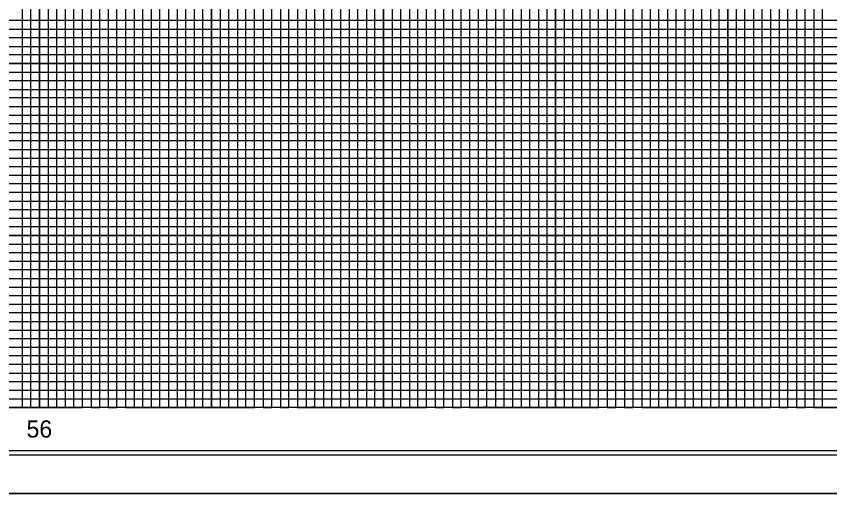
# Model space of a CAD drawing. Extents: x 1755181 to 1757273, y 729911 to 735411.
# Drawn here: x 1755934.2 to 1756407, y 733199.6 to 733488.3 of the extents above; entities that cross this region are included whole.
import ezdxf

# ---------------------------------------------------------------- set-up
doc = ezdxf.new("R2010")
doc.units = 0
for name, color, linetype in [('Exist Vertical Profile Horizontal Axis Label Major', 7, 'Continuous'), ('Scratch_Level_3', 7, 'Continuous'), ('Sheet Cutting Line CELL', 7, 'Continuous'), ('Sheet DOT Grid CELL', 7, 'Continuous'), ('Sheet Plot Border Inside CELL', 7, 'Continuous'), ('Sheet Plot Border Outside CELL', 7, 'Continuous'), ('Sheet Profile CELL', 7, 'Continuous'), ('Sheet Profile Grid Major CELL', 7, 'Continuous'), ('Sheet Profile Grid Middle CELL', 7, 'Continuous'), ('Sheet Profile Grid Minor CELL', 7, 'Continuous')]:
    doc.layers.add(name, color=color, linetype=linetype)

msp = doc.modelspace()

# ---------------------------------------------------------------- linework, layer by layer
at = {"layer": 'Scratch_Level_3'}
msp.add_lwpolyline([(1755397.67, 733760.78), (1756847.67, 733760.78), (1756847.67, 733260.78), (1755397.67, 733260.78)], close=True, dxfattribs=at)
at = {"layer": 'Sheet Cutting Line CELL'}
msp.add_line((1755180.67, 733210.78), (1756864.67, 733210.78), dxfattribs=at)
at = {"layer": 'Sheet DOT Grid CELL'}
for p, q in [((1755947.67, 733760.78), (1755947.67, 733260.78)), ((1755997.67, 733760.78), (1755997.67, 733260.78)), ((1756047.67, 733760.78), (1756047.67, 733260.78)), ((1756097.67, 733760.78), (1756097.67, 733260.78)), ((1756147.67, 733760.78), (1756147.67, 733260.78)), ((1756197.67, 733760.78), (1756197.67, 733260.78)), ((1756247.67, 733760.78), (1756247.67, 733260.78)), ((1756297.67, 733760.78), (1756297.67, 733260.78)), ((1756347.67, 733760.78), (1756347.67, 733260.78)), ((1756397.67, 733760.78), (1756397.67, 733260.78)), ((1755347.67, 733460.78), (1756847.56, 733460.78)), ((1755347.67, 733410.78), (1756847.56, 733410.78)), ((1755347.67, 733360.78), (1756847.56, 733360.78)), ((1755347.67, 733310.78), (1756847.56, 733310.78))]:
    msp.add_line(p, q, dxfattribs=at)
at = {"layer": 'Sheet Plot Border Inside CELL'}
msp.add_lwpolyline([(1755193.67, 733233.23), (1756860.17, 733233.23), (1756860.17, 734288.33), (1755193.67, 734288.33)], close=True, dxfattribs=at)
at = {"layer": 'Sheet Plot Border Outside CELL'}
for points in [[(1755180.67, 733210.78), (1756864.67, 733210.78), (1756864.67, 734310.78), (1755180.67, 734310.78)], [(1755180.67, 732110.78), (1756864.67, 732110.78), (1756864.67, 733210.78), (1755180.67, 733210.78)]]:
    msp.add_lwpolyline(points, close=True, dxfattribs=at)
at = {"layer": 'Sheet Profile CELL'}
for p, q in [((1756847.67, 733260.78), (1755347.67, 733260.78)), ((1755347.67, 733235.78), (1756847.67, 733235.78))]:
    msp.add_line(p, q, dxfattribs=at)
msp.add_lwpolyline([(1756847.67, 734285.78), (1755347.67, 734285.78), (1755347.67, 733235.78), (1756847.67, 733235.78)], close=True, dxfattribs=at)
at = {"layer": 'Sheet Profile Grid Major CELL'}
for points in [[(1755897.67, 733260.78), (1755947.67, 733260.78), (1755947.67, 733760.78), (1755997.67, 733760.78), (1755997.67, 733260.78), (1756047.67, 733260.78), (1756047.67, 733760.78), (1756097.67, 733760.78), (1756097.67, 733260.78), (1756147.67, 733260.78), (1756147.67, 733760.78), (1756197.67, 733760.78), (1756197.67, 733260.78), (1756247.67, 733260.78), (1756247.67, 733760.78), (1756297.67, 733760.78), (1756297.67, 733260.78), (1756347.67, 733260.78), (1756347.67, 733760.78), (1756397.67, 733760.78), (1756397.67, 733260.78), (1756447.67, 733260.78)], [(1756847.67, 733460.78), (1755347.67, 733460.78), (1755347.67, 733410.78), (1756847.67, 733410.78)], [(1756847.67, 733360.78), (1755347.67, 733360.78), (1755347.67, 733360.78), (1755347.67, 733310.78), (1756847.67, 733310.78)], [(1756847.67, 733260.78), (1755347.67, 733260.78)]]:
    msp.add_lwpolyline(points, dxfattribs=at)
at = {"layer": 'Sheet Profile Grid Middle CELL'}
for points in [[(1755922.67, 733260.78), (1755972.67, 733260.78), (1755972.67, 733260.78), (1755972.67, 733760.78), (1756022.67, 733760.78), (1756022.67, 733760.78)], [(1755972.67, 733760.78), (1755972.67, 733760.78), (1756022.67, 733760.78), (1756022.67, 733260.78), (1756072.67, 733260.78), (1756072.67, 733760.78), (1756122.67, 733760.78), (1756122.67, 733260.78), (1756172.67, 733260.78), (1756172.67, 733760.78), (1756222.67, 733760.78), (1756222.67, 733260.78), (1756272.67, 733260.78), (1756272.67, 733760.78), (1756322.67, 733760.78), (1756322.67, 733260.78), (1756372.67, 733260.78), (1756372.67, 733760.78), (1756422.67, 733760.78)], [(1756072.67, 733760.78), (1756072.67, 733760.78), (1756122.67, 733760.78), (1756122.67, 733260.78), (1756172.67, 733260.78), (1756172.67, 733760.78), (1756222.67, 733760.78), (1756222.67, 733260.78), (1756272.67, 733260.78), (1756272.67, 733760.78), (1756322.67, 733760.78), (1756322.67, 733260.78), (1756372.67, 733260.78), (1756372.67, 733760.78), (1756422.67, 733760.78)], [(1756097.67, 733485.78), (1755347.67, 733485.78), (1755347.67, 733435.78), (1756097.67, 733435.78)], [(1756847.67, 733485.78), (1756097.66, 733485.78)], [(1756097.66, 733435.78), (1756847.67, 733435.78)], [(1756097.67, 733385.78), (1755347.67, 733385.78), (1755347.67, 733335.78), (1756097.67, 733335.78)], [(1756847.67, 733385.78), (1756097.66, 733385.78)], [(1756097.66, 733335.78), (1756847.67, 733335.78)], [(1756097.67, 733285.78), (1755347.67, 733285.78)], [(1756847.67, 733285.78), (1756097.66, 733285.78)]]:
    msp.add_lwpolyline(points, dxfattribs=at)
at = {"layer": 'Sheet Profile Grid Minor CELL'}
for p, q in [((1755397.67, 733480.78), (1756102.67, 733480.78)), ((1756047.67, 733480.78), (1756047.67, 733480.78)), ((1756097.66, 733480.78), (1756797.67, 733480.78)), ((1756102.67, 733475.78), (1755397.67, 733475.78)), ((1756047.67, 733475.78), (1756047.67, 733475.78)), ((1756797.67, 733475.78), (1756097.66, 733475.78)), ((1755397.67, 733470.78), (1756102.67, 733470.78)), ((1756047.67, 733470.78), (1756047.67, 733470.78)), ((1756097.66, 733470.78), (1756797.67, 733470.78)), ((1756102.67, 733465.78), (1755397.67, 733465.78)), ((1756047.67, 733465.78), (1756047.67, 733465.78)), ((1756797.67, 733465.78), (1756097.66, 733465.78)), ((1755397.67, 733455.78), (1756102.67, 733455.78)), ((1756047.67, 733455.78), (1756047.67, 733455.78)), ((1756097.66, 733455.78), (1756797.67, 733455.78)), ((1756102.67, 733450.78), (1755397.67, 733450.78)), ((1756047.67, 733450.78), (1756047.67, 733450.78)), ((1756797.67, 733450.78), (1756097.66, 733450.78)), ((1755397.67, 733445.78), (1756102.67, 733445.78)), ((1756047.67, 733445.78), (1756047.67, 733445.78)), ((1756097.66, 733445.78), (1756797.67, 733445.78)), ((1756102.67, 733440.78), (1755397.67, 733440.78)), ((1756047.67, 733440.78), (1756047.67, 733440.78)), ((1756797.67, 733440.78), (1756097.66, 733440.78)), ((1755397.67, 733430.78), (1756102.67, 733430.78)), ((1756047.67, 733430.78), (1756047.67, 733430.78)), ((1756097.66, 733430.78), (1756797.67, 733430.78)), ((1756102.67, 733425.78), (1755397.67, 733425.78)), ((1756047.67, 733425.78), (1756047.67, 733425.78)), ((1756797.67, 733425.78), (1756097.66, 733425.78)), ((1755397.67, 733420.78), (1756102.67, 733420.78)), ((1756047.67, 733420.78), (1756047.67, 733420.78)), ((1756097.66, 733420.78), (1756797.67, 733420.78)), ((1756102.67, 733415.78), (1755397.67, 733415.78)), ((1756047.67, 733415.78), (1756047.67, 733415.78)), ((1756797.67, 733415.78), (1756097.66, 733415.78)), ((1755397.67, 733405.78), (1756102.67, 733405.78)), ((1756047.67, 733405.78), (1756047.67, 733405.78)), ((1756097.66, 733405.78), (1756797.67, 733405.78)), ((1756102.67, 733400.78), (1755397.67, 733400.78)), ((1756047.67, 733400.78), (1756047.67, 733400.78)), ((1756797.67, 733400.78), (1756097.66, 733400.78)), ((1755397.67, 733395.78), (1756102.67, 733395.78)), ((1756047.67, 733395.78), (1756047.67, 733395.78)), ((1756097.66, 733395.78), (1756797.67, 733395.78)), ((1756102.67, 733390.78), (1755397.67, 733390.78)), ((1756047.67, 733390.78), (1756047.67, 733390.78)), ((1756797.67, 733390.78), (1756097.66, 733390.78)), ((1755397.67, 733380.78), (1756102.67, 733380.78)), ((1756047.67, 733380.78), (1756047.67, 733380.78)), ((1756097.66, 733380.78), (1756797.67, 733380.78)), ((1756102.67, 733375.78), (1755397.67, 733375.78)), ((1756047.67, 733375.78), (1756047.67, 733375.78)), ((1756797.67, 733375.78), (1756097.66, 733375.78)), ((1755397.67, 733370.78), (1756102.67, 733370.78)), ((1756047.67, 733370.78), (1756047.67, 733370.78)), ((1756097.66, 733370.78), (1756797.67, 733370.78)), ((1756102.67, 733365.78), (1755397.67, 733365.78)), ((1756047.67, 733365.78), (1756047.67, 733365.78)), ((1756797.67, 733365.78), (1756097.66, 733365.78)), ((1755397.67, 733355.78), (1756102.67, 733355.78)), ((1756047.67, 733355.78), (1756047.67, 733355.78)), ((1756097.66, 733355.78), (1756797.67, 733355.78)), ((1756102.67, 733350.78), (1755397.67, 733350.78)), ((1756047.67, 733350.78), (1756047.67, 733350.78)), ((1756797.67, 733350.78), (1756097.66, 733350.78)), ((1755397.67, 733345.78), (1756102.67, 733345.78)), ((1756047.67, 733345.78), (1756047.67, 733345.78)), ((1756097.66, 733345.78), (1756797.67, 733345.78)), ((1756102.67, 733340.78), (1755397.67, 733340.78)), ((1756047.67, 733340.78), (1756047.67, 733340.78)), ((1756797.67, 733340.78), (1756097.66, 733340.78)), ((1755397.67, 733330.78), (1756102.67, 733330.78)), ((1756047.67, 733330.78), (1756047.67, 733330.78)), ((1756097.66, 733330.78), (1756797.67, 733330.78)), ((1756102.67, 733325.78), (1755397.67, 733325.78)), ((1756047.67, 733325.78), (1756047.67, 733325.78)), ((1756797.67, 733325.78), (1756097.66, 733325.78)), ((1755397.67, 733320.78), (1756102.67, 733320.78)), ((1756047.67, 733320.78), (1756047.67, 733320.78)), ((1756097.66, 733320.78), (1756797.67, 733320.78)), ((1756102.67, 733315.78), (1755397.67, 733315.78)), ((1756047.67, 733315.78), (1756047.67, 733315.78)), ((1756797.67, 733315.78), (1756097.66, 733315.78)), ((1755397.67, 733305.78), (1756102.67, 733305.78)), ((1756047.67, 733305.78), (1756047.67, 733305.78)), ((1756097.66, 733305.78), (1756797.67, 733305.78)), ((1756102.67, 733300.78), (1755397.67, 733300.78)), ((1756047.67, 733300.78), (1756047.67, 733300.78)), ((1756797.67, 733300.78), (1756097.66, 733300.78)), ((1755397.67, 733295.78), (1756102.67, 733295.78)), ((1756047.67, 733295.78), (1756047.67, 733295.78)), ((1756097.66, 733295.78), (1756797.67, 733295.78)), ((1756102.67, 733290.78), (1755397.67, 733290.78)), ((1756047.67, 733290.78), (1756047.67, 733290.78)), ((1756797.67, 733290.78), (1756097.66, 733290.78)), ((1755397.67, 733280.78), (1756102.67, 733280.78)), ((1756047.67, 733280.78), (1756047.67, 733280.78)), ((1756097.66, 733280.78), (1756797.67, 733280.78)), ((1756102.67, 733275.78), (1755397.67, 733275.78)), ((1756047.67, 733275.78), (1756047.67, 733275.78)), ((1756797.67, 733275.78), (1756097.66, 733275.78)), ((1755397.67, 733270.78), (1756102.67, 733270.78)), ((1756047.67, 733270.78), (1756047.67, 733270.78)), ((1756097.66, 733270.78), (1756797.67, 733270.78)), ((1755397.67, 733265.78), (1756102.67, 733265.78)), ((1756047.67, 733265.78), (1756047.67, 733265.78)), ((1756097.66, 733265.78), (1756797.67, 733265.78))]:
    msp.add_line(p, q, dxfattribs=at)
for points in [[(1755932.67, 733760.78), (1755937.67, 733760.78), (1755937.67, 733260.78), (1755942.67, 733260.78), (1755942.67, 733760.78), (1755952.67, 733760.78), (1755952.67, 733260.78), (1755957.67, 733260.78), (1755957.67, 733760.78), (1755962.67, 733760.78), (1755962.67, 733260.78), (1755967.67, 733260.78), (1755967.67, 733760.78), (1755977.67, 733760.78), (1755977.67, 733260.78), (1755982.67, 733260.78), (1755982.67, 733760.78), (1755987.67, 733760.78), (1755987.67, 733260.78), (1755992.67, 733260.78), (1755992.67, 733760.78), (1756002.67, 733760.78), (1756002.67, 733760.78)], [(1756002.67, 733760.78), (1756002.67, 733260.78), (1756007.67, 733260.78), (1756007.67, 733760.78)], [(1756012.67, 733760.78), (1756012.67, 733260.78), (1756017.67, 733260.78), (1756017.67, 733760.78)], [(1756027.67, 733760.78), (1756027.67, 733260.78), (1756032.67, 733260.78), (1756032.67, 733760.78)], [(1756037.67, 733760.78), (1756037.67, 733260.78), (1756042.67, 733260.78), (1756042.67, 733760.78)], [(1756052.67, 733760.78), (1756052.67, 733260.78), (1756057.67, 733260.78), (1756057.67, 733760.78)], [(1756062.67, 733760.78), (1756062.67, 733260.78), (1756067.67, 733260.78), (1756067.67, 733760.78)], [(1756077.67, 733760.78), (1756077.67, 733260.78), (1756082.67, 733260.78), (1756082.67, 733760.78)], [(1756087.67, 733760.78), (1756087.67, 733260.78), (1756092.67, 733260.78), (1756092.67, 733760.78)], [(1756102.67, 733760.78), (1756102.67, 733260.78), (1756107.67, 733260.78), (1756107.67, 733760.78)], [(1756102.67, 733760.78), (1756102.67, 733260.78), (1756107.37, 733261.33), (1756107.67, 733260.78), (1756107.67, 733760.78)], [(1756112.67, 733760.78), (1756112.67, 733260.78), (1756117.67, 733260.78), (1756117.67, 733760.78)], [(1756112.67, 733760.78), (1756112.67, 733260.78), (1756117.67, 733260.78), (1756117.67, 733760.78)], [(1756127.67, 733760.78), (1756127.67, 733260.78), (1756132.67, 733260.78), (1756132.67, 733760.78)], [(1756127.67, 733760.78), (1756127.67, 733260.78), (1756132.67, 733260.78)], [(1756137.67, 733760.78), (1756137.67, 733260.78), (1756142.67, 733260.78), (1756142.67, 733760.78)], [(1756152.67, 733760.78), (1756152.67, 733260.78), (1756157.67, 733260.78), (1756157.67, 733760.78)], [(1756162.67, 733760.78), (1756162.67, 733260.78), (1756167.67, 733260.78), (1756167.67, 733760.78)], [(1756177.67, 733760.78), (1756177.67, 733260.78), (1756182.67, 733260.78), (1756182.67, 733760.78)], [(1756187.67, 733760.78), (1756187.67, 733260.78), (1756192.67, 733260.78), (1756192.67, 733760.78)], [(1756202.67, 733760.78), (1756202.67, 733260.78), (1756207.37, 733261.33), (1756207.67, 733260.78), (1756207.67, 733760.78)], [(1756212.67, 733760.78), (1756212.67, 733260.78), (1756217.67, 733260.78), (1756217.67, 733760.78)], [(1756227.67, 733760.78), (1756227.67, 733260.78), (1756232.67, 733260.78)], [(1756232.67, 733260.78), (1756232.67, 733760.78)], [(1756237.67, 733760.78), (1756237.67, 733260.78), (1756242.67, 733260.78), (1756242.67, 733760.78)], [(1756252.67, 733760.78), (1756252.67, 733260.78), (1756257.67, 733260.78), (1756257.67, 733760.78)], [(1756262.67, 733760.78), (1756262.67, 733260.78), (1756267.67, 733260.78), (1756267.67, 733760.78)], [(1756277.67, 733760.78), (1756277.67, 733260.78), (1756282.67, 733260.78), (1756282.67, 733760.78)], [(1756287.67, 733760.78), (1756287.67, 733260.78), (1756292.67, 733260.78), (1756292.67, 733760.78)], [(1756302.67, 733760.78), (1756302.67, 733260.78), (1756307.67, 733260.78), (1756307.67, 733760.78)], [(1756312.67, 733760.78), (1756312.67, 733260.78), (1756317.67, 733260.78), (1756317.67, 733760.78)], [(1756327.67, 733760.78), (1756327.67, 733260.78), (1756332.67, 733260.78), (1756332.67, 733760.78)], [(1756337.67, 733760.78), (1756337.67, 733260.78), (1756342.67, 733260.78), (1756342.67, 733760.78)], [(1756352.67, 733760.78), (1756352.67, 733260.78), (1756357.67, 733260.78), (1756357.67, 733760.78)], [(1756362.67, 733760.78), (1756362.67, 733260.78), (1756367.67, 733260.78), (1756367.67, 733760.78)], [(1756377.67, 733760.78), (1756377.67, 733260.78), (1756382.67, 733260.78), (1756382.67, 733760.78)], [(1756387.67, 733760.78), (1756387.67, 733260.78), (1756392.67, 733260.78), (1756392.67, 733760.78)], [(1756402.67, 733760.78), (1756402.67, 733260.78), (1756407.67, 733260.78)], [(1756002.67, 733260.79), (1756002.67, 733260.78), (1756007.67, 733260.78), (1756007.67, 733260.79)], [(1756012.67, 733260.79), (1756012.67, 733260.78), (1756017.67, 733260.78), (1756017.67, 733260.79)], [(1756027.67, 733260.79), (1756027.67, 733260.78), (1756032.67, 733260.78), (1756032.67, 733260.79)], [(1756037.67, 733260.79), (1756037.67, 733260.78), (1756042.67, 733260.78), (1756042.67, 733260.79)], [(1756052.67, 733260.79), (1756052.67, 733260.78), (1756052.67, 733260.78), (1756057.67, 733260.78), (1756057.67, 733260.79)], [(1756062.67, 733260.79), (1756062.67, 733260.78), (1756067.67, 733260.78), (1756067.67, 733260.79)], [(1756077.67, 733260.79), (1756077.67, 733260.78), (1756082.67, 733260.78), (1756082.67, 733260.79)], [(1756087.67, 733260.79), (1756087.67, 733260.78), (1756092.67, 733260.78), (1756092.67, 733260.79)]]:
    msp.add_lwpolyline(points, dxfattribs=at)

# ---------------------------------------------------------------- texts
at = {"layer": 'Exist Vertical Profile Horizontal Axis Label Major'}
msp.add_text('56', height=10, dxfattribs=at).set_placement((1755940.15, 733243.28))

doc.saveas('drawing.dxf')
